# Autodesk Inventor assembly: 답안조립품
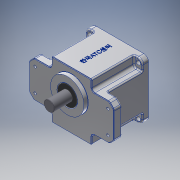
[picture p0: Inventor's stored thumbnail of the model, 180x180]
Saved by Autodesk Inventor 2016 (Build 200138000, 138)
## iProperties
Created: 2017-01
Part Number: 답안조립품
Material: 일반
Document SubType Name: Assembly
Designer: Owner
Author: Owner
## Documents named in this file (10)
- E:\470111V1002\답안조립품.iam
- E:\470111V1002\본체.ipt
- E:\470111V1002\메인축.ipt
- E:\470111V1002\베어링 608.ipt
- E:\470111V1002\베어링 6003.ipt
- E:\470111V1002\볼트 M4 x 10.ipt
- E:\470111V1002\서브축.ipt
- E:\470111V1002\오일실 8 22 7.ipt
- E:\470111V1002\오일실 17 32 8.ipt
- E:\470111V1002\커버.ipt
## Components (2 placed, 1 different names)
1. ISO 4762 M4 x 10:1
2. ISO 4762 M4 x 10:2
